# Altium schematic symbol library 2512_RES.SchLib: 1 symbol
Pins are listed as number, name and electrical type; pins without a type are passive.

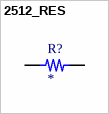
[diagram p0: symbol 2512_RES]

## 2512_RES
designator R?
MF: Bourns; MP: CR2512AJ/-000EAS
footprint 2512
pins: 1, 2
